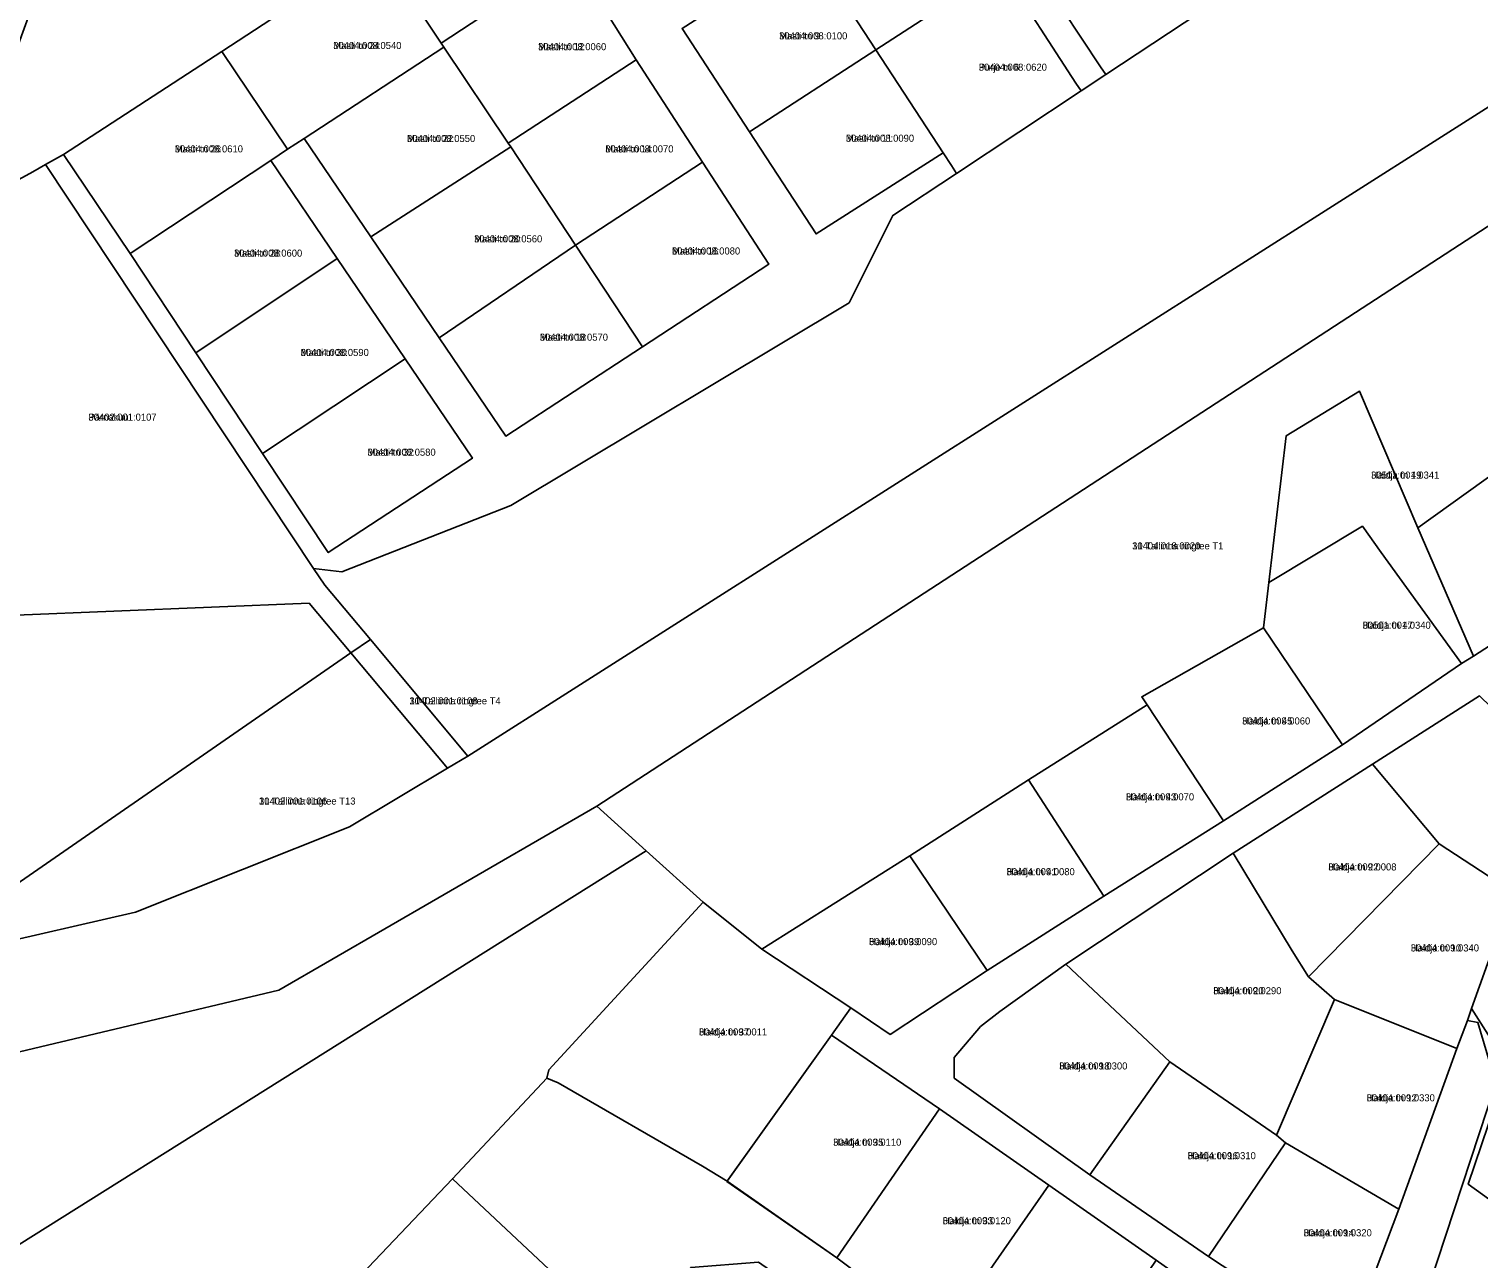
# Model space of a CAD drawing. Extents: x 542681 to 554572, y 6566489 to 6580482.
# Drawn here: x 543954 to 544262.4, y 6576451.7 to 6576713.2 of the extents above; entities that cross this region are included whole.
import ezdxf

# ---------------------------------------------------------------- set-up
doc = ezdxf.new("R2010")
doc.units = 0
for name, color, linetype in [('L_AADRESS', 7, 'Continuous'), ('PIIR', 7, 'Continuous'), ('TUNNUS', 7, 'Continuous')]:
    doc.layers.add(name, color=color, linetype=linetype)

msp = doc.modelspace()

# ---------------------------------------------------------------- linework, layer by layer
at = {"layer": 'PIIR'}
for points in [[(543943.88, 6576517.87), (543976.64, 6576525.41), (544022.17, 6576543.56), (544043.03, 6576556), (544047.37, 6576558.6), (544511.03, 6576853.43)], [(544511.03, 6576853.43), (544047.37, 6576558.6), (544026.62, 6576583.38), (544016.91, 6576594.91), (544014.54, 6576598.48), (544020.55, 6576597.73), (544056.47, 6576611.84), (544128.46, 6576654.95), (544137.76, 6576673.53), (544151.28, 6576682.47), (544177.78, 6576699.99), (544183.03, 6576703.47), (544209.73, 6576721.14)], [(544353.21, 6576726.8), (544302.38, 6576695.41), (544289.35, 6576687.48), (544074.8, 6576547.93), (544007.14, 6576508.85), (543946.22, 6576494.37)], [(544092.9, 6576713.29), (544107.24, 6576691.31), (544121.4, 6576669.61), (544148.44, 6576686.82), (544150.19, 6576684.14), (544151.28, 6576682.47), (544137.76, 6576673.53), (544128.46, 6576654.95), (544056.47, 6576611.84), (544020.55, 6576597.73), (544014.54, 6576598.48), (543957.54, 6576684.34), (543961.37, 6576686.48), (543975.49, 6576665.45), (543989.52, 6576644.31), (544003.7, 6576622.92), (544017.67, 6576601.86), (544048.33, 6576621.92), (544034.03, 6576643.02), (544019.56, 6576664.38), (544005.42, 6576685.23), (544009.01, 6576687.6), (544012.53, 6576689.9), (544026.72, 6576668.96), (544041.25, 6576647.52), (544055.44, 6576626.57), (544084.49, 6576645.57), (544111.35, 6576663.14), (544097.25, 6576684.87), (544083.14, 6576706.63), (544069.43, 6576728.43)], [(544165.77, 6576729.54), (544181.93, 6576705.13), (544183.03, 6576703.47), (544177.78, 6576699.99), (544176.69, 6576701.67), (544160.86, 6576726.12)], [(544286.61, 6576441.29), (544257.79, 6576433.83), (544242.57, 6576429.7), (544235.52, 6576429.45), (544222.25, 6576431.22), (544216.21, 6576435.56), (544193.76, 6576451.43), (544170.89, 6576467.39), (544147.64, 6576483.61), (544124.67, 6576499.26), (544128.83, 6576505.05), (544137.15, 6576499.41), (544157.82, 6576512.98), (544182.59, 6576528.83), (544208.09, 6576544.83), (544233.35, 6576561), (544258.69, 6576578.28), (544261.23, 6576579.8), (544289.09, 6576597.81)], [(544262.49, 6576571.37), (544239.79, 6576556.86), (544210.12, 6576537.92), (544174.56, 6576514.35), (544160.49, 6576504.28), (544156.37, 6576501.1), (544150.76, 6576494.53), (544150.8, 6576490.14), (544179.63, 6576469.59), (544204.88, 6576452.2), (544227.47, 6576437.3), (544236.48, 6576438.83), (544245.33, 6576462.28), (544257.69, 6576496.4), (544259.96, 6576502.39), (544262.2, 6576501.99), (544265.96, 6576489.08), (544249.95, 6576440.39), (544282.82, 6576447.7)]]:
    msp.add_lwpolyline(points, dxfattribs=at)
for points in [[(543973.39, 6576769.78), (543953.11, 6576776.64), (543964.99, 6576814.08), (543974.95, 6576802.11), (543981.99, 6576791.82), (543985.82, 6576794.41), (543994.87, 6576782.5), (544009.2, 6576760.05), (544012.45, 6576754.96), (544027, 6576732.31), (544028.33, 6576730.2), (543995.02, 6576708.39), (543961.37, 6576686.48), (543957.54, 6576684.34), (543954.8, 6576682.81), (543948.88, 6576679.53), (543821.12, 6576608.68), (543839.75, 6576654.18), (543848.49, 6576677.12), (543870.89, 6576733.03), (543949.95, 6576704.85)], [(544028.33, 6576730.2), (544027, 6576732.31), (544055.16, 6576751.13), (544069.43, 6576728.43), (544041.69, 6576710.13)], [(544119.88, 6576730.59), (544146.56, 6576748.25), (544160.86, 6576726.12), (544134.12, 6576708.76)], [(544181.93, 6576705.13), (544165.77, 6576729.54), (544192.54, 6576747.26), (544208.5, 6576723.01), (544209.73, 6576721.14), (544183.03, 6576703.47)], [(544009.01, 6576687.6), (543995.02, 6576708.39), (544028.33, 6576730.2), (544041.69, 6576710.13), (544042.25, 6576709.3), (544012.53, 6576689.9)], [(544134.12, 6576708.76), (544107.24, 6576691.31), (544092.9, 6576713.29), (544119.88, 6576730.59)], [(544042.25, 6576709.3), (544041.69, 6576710.13), (544069.43, 6576728.43), (544083.14, 6576706.63), (544055.95, 6576688.87)], [(544150.19, 6576684.14), (544148.44, 6576686.82), (544134.12, 6576708.76), (544160.86, 6576726.12), (544176.69, 6576701.67), (544177.78, 6576699.99), (544151.28, 6576682.47)], [(543961.37, 6576686.48), (543995.02, 6576708.39), (544009.01, 6576687.6), (544005.42, 6576685.23), (543975.49, 6576665.45)], [(544012.53, 6576689.9), (544042.25, 6576709.3), (544055.95, 6576688.87), (544056.47, 6576688.08), (544026.72, 6576668.96)], [(544107.24, 6576691.31), (544134.12, 6576708.76), (544148.44, 6576686.82), (544121.4, 6576669.61)], [(544056.47, 6576688.08), (544055.95, 6576688.87), (544083.14, 6576706.63), (544097.25, 6576684.87), (544070.23, 6576667.21)], [(544026.72, 6576668.96), (544056.47, 6576688.08), (544070.23, 6576667.21), (544041.25, 6576647.52)], [(544289.35, 6576687.48), (544317.08, 6576657.44), (544294.75, 6576639.67), (544249.38, 6576607.13), (544236.97, 6576636.2), (544221.4, 6576626.7), (544217.71, 6576595.47), (544216.61, 6576585.87), (544190.69, 6576571.22), (544191.83, 6576569.51), (544166.57, 6576553.56), (544141.37, 6576537.4), (544109.87, 6576517.58), (544097.38, 6576527.56), (544085.24, 6576538.48), (544074.8, 6576547.93)], [(543948.88, 6576679.53), (543954.8, 6576682.81), (543957.54, 6576684.34), (544014.54, 6576598.48), (544016.91, 6576594.91), (544026.62, 6576583.38), (544022.47, 6576580.55), (544013.59, 6576591.12), (543909.63, 6576586.83), (543906.67, 6576591.6)], [(543975.49, 6576665.45), (544005.42, 6576685.23), (544019.56, 6576664.38), (543989.52, 6576644.31)], [(544070.23, 6576667.21), (544097.25, 6576684.87), (544111.35, 6576663.14), (544084.49, 6576645.57)], [(543864.11, 6576518.16), (543826.75, 6576533.72), (543818.92, 6576546.85), (543810.8, 6576582.34), (543821.12, 6576608.68), (543948.88, 6576679.53), (543906.67, 6576591.6), (543909.63, 6576586.83), (544013.59, 6576591.12), (544022.47, 6576580.55), (543929.08, 6576516), (543907.07, 6576513.79)], [(544041.25, 6576647.52), (544070.23, 6576667.21), (544084.49, 6576645.57), (544055.44, 6576626.57)], [(543989.52, 6576644.31), (544019.56, 6576664.38), (544034.03, 6576643.02), (544003.7, 6576622.92)], [(544048.33, 6576621.92), (544017.67, 6576601.86), (544003.7, 6576622.92), (544034.03, 6576643.02)], [(544249.38, 6576607.13), (544294.75, 6576639.67), (544315.71, 6576617.49), (544317.17, 6576615.99), (544336.57, 6576594.33), (544318.03, 6576577.71), (544289.09, 6576597.81), (544261.23, 6576579.8)], [(544261.23, 6576579.8), (544258.69, 6576578.28), (544241.59, 6576601.84), (544237.61, 6576607.44), (544217.71, 6576595.47), (544221.4, 6576626.7), (544236.97, 6576636.2), (544249.38, 6576607.13)], [(544258.69, 6576578.28), (544233.35, 6576561), (544216.61, 6576585.87), (544217.71, 6576595.47), (544237.61, 6576607.44), (544241.59, 6576601.84)], [(544190.69, 6576571.22), (544216.61, 6576585.87), (544233.35, 6576561), (544208.09, 6576544.83), (544191.83, 6576569.51)], [(544022.47, 6576580.55), (544026.62, 6576583.38), (544047.37, 6576558.6), (544043.03, 6576556)], [(543929.08, 6576516), (544022.47, 6576580.55), (544043.03, 6576556), (544022.17, 6576543.56), (543976.64, 6576525.41), (543943.88, 6576517.87)], [(544166.57, 6576553.56), (544191.83, 6576569.51), (544208.09, 6576544.83), (544182.59, 6576528.83)], [(544239.79, 6576556.86), (544262.49, 6576571.37), (544284.6, 6576550.01), (544274.47, 6576528.68), (544272.03, 6576529.24), (544269.66, 6576529.68), (544253.97, 6576539.93)], [(544210.12, 6576537.92), (544239.79, 6576556.86), (544253.97, 6576539.93), (544226.17, 6576511.7), (544222.64, 6576517.16)], [(544141.37, 6576537.4), (544166.57, 6576553.56), (544182.59, 6576528.83), (544157.82, 6576512.98)], [(543758.49, 6576501.47), (543789.73, 6576517.51), (543854.56, 6576498.28), (543909.25, 6576490.8), (543946.22, 6576494.37), (544007.14, 6576508.85), (544074.8, 6576547.93), (544085.24, 6576538.48), (543870.87, 6576403.95), (543856.61, 6576424), (543829.53, 6576408.62), (543810.38, 6576393.03), (543832.23, 6576369.07), (543678.38, 6576251.99), (543610.08, 6576200.08), (543624.99, 6576231.86), (543740.67, 6576463.36)], [(544226.17, 6576511.7), (544253.97, 6576539.93), (544269.66, 6576529.68), (544260.82, 6576504.94), (544259.96, 6576502.39), (544257.69, 6576496.4), (544231.7, 6576506.88)], [(543870.87, 6576403.95), (544085.24, 6576538.48), (544097.38, 6576527.56), (544064.6, 6576491.86), (544064.17, 6576490.1), (544044.07, 6576468.75), (544009.62, 6576432.52), (543975.25, 6576396.23), (543940.66, 6576360.15), (543918.54, 6576337.02)], [(544109.87, 6576517.58), (544141.37, 6576537.4), (544157.82, 6576512.98), (544137.15, 6576499.41), (544128.83, 6576505.05)], [(544174.56, 6576514.35), (544210.12, 6576537.92), (544222.64, 6576517.18), (544226.17, 6576511.7), (544231.7, 6576506.88), (544219.36, 6576478.01), (544196.64, 6576493.6)], [(544269.66, 6576529.68), (544272.03, 6576529.24), (544274.47, 6576528.68), (544317.15, 6576514.83), (544315.5, 6576510.03), (544321.74, 6576499.42), (544312.79, 6576474.23), (544299.26, 6576459.61), (544285.27, 6576449.45), (544260.11, 6576467.58), (544268.65, 6576492.64), (544260.82, 6576504.94)], [(544097.38, 6576527.56), (544109.87, 6576517.58), (544128.83, 6576505.05), (544124.67, 6576499.26), (544102.48, 6576468.22), (544097.22, 6576471.39), (544066.59, 6576489.13), (544064.17, 6576490.1), (544064.6, 6576491.86)], [(544179.63, 6576469.59), (544150.8, 6576490.14), (544150.76, 6576494.53), (544156.37, 6576501.1), (544160.49, 6576504.28), (544174.56, 6576514.35), (544196.64, 6576493.6)], [(544231.7, 6576506.88), (544257.69, 6576496.4), (544245.33, 6576462.28), (544221.28, 6576476.4), (544219.36, 6576478.01)], [(544259.96, 6576502.39), (544260.82, 6576504.94), (544268.65, 6576492.64), (544260.11, 6576467.58), (544285.27, 6576449.45), (544282.82, 6576447.7), (544249.95, 6576440.39), (544265.96, 6576489.08), (544262.2, 6576501.99)], [(544102.43, 6576468.17), (544124.67, 6576499.26), (544147.64, 6576483.61), (544125.86, 6576451.94)], [(544179.63, 6576469.59), (544196.64, 6576493.6), (544219.36, 6576478.01), (544221.28, 6576476.4), (544204.88, 6576452.2)], [(544044.07, 6576468.75), (544064.17, 6576490.1), (544066.59, 6576489.13), (544097.22, 6576471.39), (544102.48, 6576468.22), (544125.81, 6576451.93), (544131.83, 6576447.39), (544148.37, 6576435.01), (544172.2, 6576419.65), (544181.99, 6576413.35), (544193.51, 6576403.42), (544195.85, 6576401.34), (544210.63, 6576393.14), (544207.76, 6576388.65), (544158.24, 6576416.83), (544109.18, 6576451), (544094.74, 6576449.9), (544080.52, 6576434.57)], [(544125.81, 6576451.93), (544147.64, 6576483.61), (544170.89, 6576467.39), (544148.37, 6576435.01), (544131.83, 6576447.39)], [(544221.28, 6576476.4), (544245.33, 6576462.28), (544236.48, 6576438.83), (544227.47, 6576437.3), (544204.88, 6576452.2)], [(544009.62, 6576432.52), (544044.07, 6576468.75), (544080.52, 6576434.57), (544046.36, 6576397.94)], [(544148.37, 6576435.01), (544170.89, 6576467.39), (544193.76, 6576451.43), (544172.2, 6576419.65)]]:
    msp.add_lwpolyline(points, close=True, dxfattribs=at)

# ---------------------------------------------------------------- texts
at = {"layer": 'L_AADRESS'}
for s, p in [('Masti tn 9', (544113.56, 6576710.95)), ('Masti tn 24', (544018.72, 6576708.9)), ('Masti tn 12', (544062.28, 6576708.65)), ('Purje tn 6', (544156.01, 6576704.29)), ('Masti tn 22', (544034.41, 6576689.13)), ('Masti tn 11', (544127.76, 6576689.19)), ('Masti tn 26', (543985.01, 6576686.92)), ('Masti tn 14', (544076.58, 6576686.92)), ('Masti tn 20', (544048.67, 6576667.8)), ('Masti tn 28', (543997.62, 6576664.77)), ('Masti tn 16', (544090.77, 6576665.22)), ('Masti tn 18', (544062.65, 6576646.89)), ('Masti tn 30', (544011.78, 6576643.65)), ('Pärnakuu', (543966.64, 6576629.9)), ('Masti tn 32', (544026, 6576622.44)), ('Haldja tn 49', (544239.47, 6576617.58)), ('11 Tallinna ringtee T1', (544188.64, 6576602.53)), ('Haldja tn 47', (544237.65, 6576585.66)), ('11 Tallinna ringtee T4', (544034.92, 6576569.58)), ('Haldja tn 45', (544212.02, 6576565.31)), ('11 Tallinna ringtee T13', (544002.93, 6576548.28)), ('Haldja tn 43', (544187.32, 6576549.17)), ('Haldja tn 22', (544230.36, 6576534.28)), ('Haldja tn 41', (544161.93, 6576533.27)), ('Haldja tn 39', (544132.67, 6576518.4)), ('Haldja tn 10', (544247.91, 6576517.06)), ('Haldja tn 20', (544205.9, 6576507.97)), ('Haldja tn 37', (544096.5, 6576499.2)), ('Haldja tn 18', (544173.13, 6576491.97)), ('Haldja tn 12', (544238.52, 6576485.2)), ('Haldja tn 35', (544125.04, 6576475.76)), ('Haldja tn 16', (544200.44, 6576472.9)), ('Haldja tn 33', (544148.35, 6576459.07)), ('Haldja tn 14', (544225.11, 6576456.51))]:
    msp.add_text(s, height=1.5, dxfattribs=at).set_placement(p)
at = {"layer": 'TUNNUS'}
for s, p in [('30404:008:0100', (544113.56, 6576710.95)), ('30404:008:0540', (544018.72, 6576708.9)), ('30404:008:0060', (544062.28, 6576708.65)), ('30404:008:0620', (544156.01, 6576704.29)), ('30404:008:0550', (544034.41, 6576689.13)), ('30404:008:0090', (544127.76, 6576689.19)), ('30404:008:0610', (543985.01, 6576686.92)), ('30404:008:0070', (544076.58, 6576686.92)), ('30404:008:0560', (544048.67, 6576667.8)), ('30404:008:0600', (543997.62, 6576664.77)), ('30404:008:0080', (544090.77, 6576665.22)), ('30404:008:0570', (544062.65, 6576646.89)), ('30404:008:0590', (544011.78, 6576643.65)), ('30402:001:0107', (543966.64, 6576629.9)), ('30404:008:0580', (544026, 6576622.44)), ('30501:001:0341', (544239.47, 6576617.58)), ('30404:018:0020', (544188.64, 6576602.53)), ('30501:001:0340', (544237.65, 6576585.66)), ('30402:001:0108', (544034.92, 6576569.58)), ('30404:009:0060', (544212.02, 6576565.31)), ('30402:001:0106', (544002.93, 6576548.28)), ('30404:009:0070', (544187.32, 6576549.17)), ('30404:009:0008', (544230.36, 6576534.28)), ('30404:009:0080', (544161.93, 6576533.27)), ('30404:009:0090', (544132.67, 6576518.4)), ('30404:009:0340', (544247.91, 6576517.06)), ('30404:009:0290', (544205.9, 6576507.97)), ('30404:009:0011', (544096.5, 6576499.2)), ('30404:009:0300', (544173.13, 6576491.97)), ('30404:009:0330', (544238.52, 6576485.2)), ('30404:009:0110', (544125.04, 6576475.76)), ('30404:009:0310', (544200.44, 6576472.9)), ('30404:009:0120', (544148.35, 6576459.07)), ('30404:009:0320', (544225.11, 6576456.51))]:
    msp.add_text(s, height=1.5, dxfattribs=at).set_placement(p)

doc.saveas('drawing.dxf')
